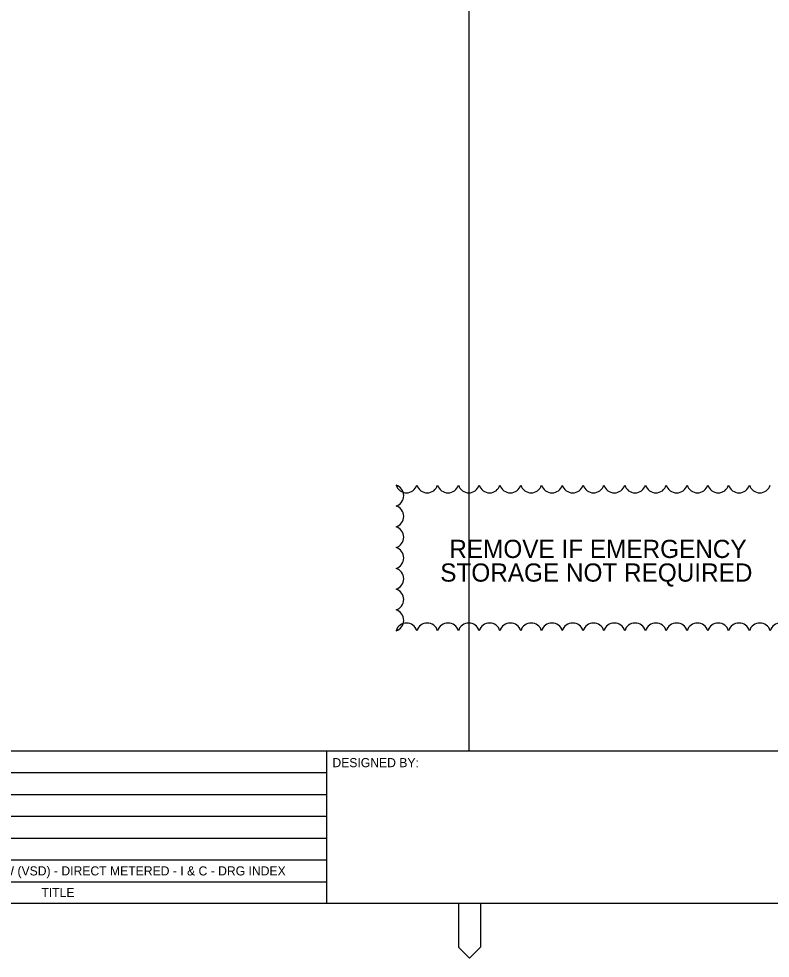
# Model space of a CAD drawing. Extents: x 0 to 841, y 0 to 594.
# Drawn here: x 296.3 to 502.9, y 0 to 258.2 of the extents above; entities that cross this region are included whole.
import ezdxf

# ---------------------------------------------------------------- set-up
doc = ezdxf.new("R2010")
doc.units = 0
doc.layers.add('A1BORDER', color=7, linetype='Continuous')
doc.layers.add('Level 1', color=7, linetype='Continuous')

msp = doc.modelspace()

# ---------------------------------------------------------------- linework, layer by layer
at = {"layer": 'A1BORDER'}
for p, q in [((28, 57), (829, 57)), ((381, 15), (381, 57)), ((213, 51), (381, 51)), ((213, 45), (381, 45)), ((213, 39), (381, 39)), ((213, 33), (381, 33)), ((213, 27), (381, 27)), ((213, 21), (381, 21)), ((829, 15), (28, 15)), ((417.19, 15), (417.19, 3)), ((423.19, 15), (423.19, 3)), ((417.19, 3), (420.19, 0)), ((423.19, 3), (420.19, 0))]:
    msp.add_line(p, q, dxfattribs=at)
at = {"layer": 'Level 1'}
msp.add_line((420, 572.5), (420, 57), dxfattribs=at)
for centre, start, end in [((402.86, 130.9), 197.5, 342.5), ((399.1, 127.14), 287.5, 72.5), ((408.57, 130.9), 197.5, 342.5), ((414.29, 130.9), 197.5, 342.5), ((420, 130.9), 197.5, 342.5), ((425.71, 130.9), 197.5, 342.5), ((431.43, 130.9), 197.5, 342.5), ((437.14, 130.9), 197.5, 342.5), ((442.86, 130.9), 197.5, 342.5), ((448.57, 130.9), 197.5, 342.5), ((454.29, 130.9), 197.5, 342.5), ((460, 130.9), 197.5, 342.5), ((465.71, 130.9), 197.5, 342.5), ((471.43, 130.9), 197.5, 342.5), ((477.14, 130.9), 197.5, 342.5), ((482.86, 130.9), 197.5, 342.5), ((488.57, 130.9), 197.5, 342.5), ((494.29, 130.9), 197.5, 342.5), ((500, 130.9), 197.5, 342.5), ((399.1, 121.43), 287.5, 72.5), ((399.1, 115.71), 287.5, 72.5), ((399.1, 110), 287.5, 72.5), ((399.1, 104.29), 287.5, 72.5), ((399.1, 98.57), 287.5, 72.5), ((399.1, 92.86), 287.5, 72.5), ((402.86, 89.1), 17.5, 162.5), ((408.57, 89.1), 17.5, 162.5), ((414.29, 89.1), 17.5, 162.5), ((420, 89.1), 17.5, 162.5), ((425.71, 89.1), 17.5, 162.5), ((431.43, 89.1), 17.5, 162.5), ((437.14, 89.1), 17.5, 162.5), ((442.86, 89.1), 17.5, 162.5), ((448.57, 89.1), 17.5, 162.5), ((454.29, 89.1), 17.5, 162.5), ((460, 89.1), 17.5, 162.5), ((465.71, 89.1), 17.5, 162.5), ((471.43, 89.1), 17.5, 162.5), ((477.14, 89.1), 17.5, 162.5), ((482.86, 89.1), 17.5, 162.5), ((488.57, 89.1), 17.5, 162.5), ((494.29, 89.1), 17.5, 162.5), ((500, 89.1), 17.5, 162.5), ((505.71, 89.1), 17.5, 162.5)]:
    msp.add_arc(centre, 3, start, end, dxfattribs=at)

# ---------------------------------------------------------------- texts
at = {"layer": 'A1BORDER'}
for s, p in [('DESIGNED BY:', (382.5, 52.5)), ('TITLE', (302.5, 16.81))]:
    msp.add_text(s, height=2.5, dxfattribs=at).set_placement(p)
at = {"layer": 'Level 1'}
for s, height, p in [('REMOVE IF EMERGENCY', 5, (414.64, 110)), ('STORAGE NOT REQUIRED', 5, (412.15, 103.5)), ('STD SPS - PUMP STN 7.5kW TO 22kW (VSD) - DIRECT METERED - I & C - DRG INDEX', 2.5, (235, 22.75))]:
    msp.add_text(s, height=height, dxfattribs=at).set_placement(p)

doc.saveas('drawing.dxf')
